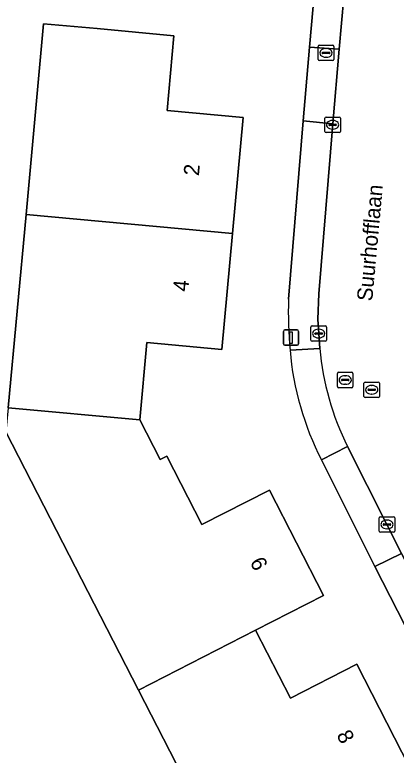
# Model space of a CAD drawing. Extents: x 162722 to 165104, y 384719 to 386284.
# Drawn here: x 163926.07 to 163950.78, y 385101.85 to 385149.88 of the extents above; entities that cross this region are included whole.
import ezdxf

# ---------------------------------------------------------------- set-up
doc = ezdxf.new("R2010")
doc.units = 0
for name, color, linetype in [('IMGEO_Brandkraan', 7, 'Continuous'), ('IMGEO_Erf', 7, 'Continuous'), ('IMGEO_Kolk', 7, 'Continuous'), ('IMGEO_Lichtmast', 7, 'Continuous'), ('IMGEO_Openbare_ruimte_label', 7, 'Continuous'), ('IMGEO_Pand', 7, 'Continuous'), ('IMGEO_Pand_nummerreeks', 7, 'Continuous'), ('IMGEO_Parkeervlak_open', 7, 'Continuous'), ('IMGEO_Rijbaan_lokaal_gesloten', 7, 'Continuous'), ('IMGEO_Rioolput', 7, 'Continuous'), ('IMGEO_Voetpad_open', 7, 'Continuous')]:
    doc.layers.add(name, color=color, linetype=linetype)

msp = doc.modelspace()

# ---------------------------------------------------------------- linework, layer by layer
at = {"layer": 'IMGEO_Brandkraan'}
for p, q in [((163945.732, 385146.978), (163945.732, 385147.83)), ((163945.807, 385147.904), (163946.659, 385147.904)), ((163946.22, 385147.684), (163946.245, 385147.684)), ((163946.733, 385147.83), (163946.733, 385146.978)), ((163945.991, 385147.398), (163945.991, 385147.41)), ((163946.429, 385147.361), (163946.031, 385147.361)), ((163946.034, 385147.447), (163946.432, 385147.447)), ((163946.475, 385147.41), (163946.475, 385147.398)), ((163946.659, 385146.904), (163945.807, 385146.904)), ((163946.243, 385147.124), (163946.218, 385147.124))]:
    msp.add_line(p, q, dxfattribs=at)
for points in [[(163945.732, 385146.978), (163945.732, 385147.83)], [(163945.807, 385147.904), (163946.659, 385147.904)], [(163946.733, 385147.83), (163946.733, 385146.978)], [(163946.659, 385146.904), (163945.807, 385146.904)]]:
    msp.add_lwpolyline(points, dxfattribs=at)
for centre, radius, start, end in [((163945.809, 385147.828), 0.0765, 91.552, 178.448), ((163945.809, 385147.828), 0.0765, 91.552, 178.448), ((163946.657, 385147.828), 0.0765, 1.552, 88.448), ((163946.657, 385147.828), 0.0765, 1.552, 88.448), ((163946.031, 385147.407), 0.0403, 85.8775, 175.7526), ((163946.028, 385147.397), 0.0366, 178.938, 274.7102), ((163946.432, 385147.404), 0.043, 264.8664, 352.4533), ((163946.436, 385147.409), 0.0386, 1.7309, 96.639), ((163945.809, 385146.98), 0.0765, 181.552, 268.448), ((163945.809, 385146.98), 0.0765, 181.552, 268.448), ((163946.657, 385146.98), 0.0765, 271.552, 358.448), ((163946.657, 385146.98), 0.0765, 271.552, 358.448)]:
    msp.add_arc(centre, radius, start, end, dxfattribs=at)
for centre, major_axis, ratio, start_param, end_param in [((163946.219, 385147.404), (-0.387, 0.002), 0.722429, 4.712389, 7.853982), ((163946.244, 385147.404), (-0.39, 0.002), 0.717154, 1.570796, 4.712389)]:
    msp.add_ellipse(centre, major_axis=major_axis, ratio=ratio, start_param=start_param, end_param=end_param, dxfattribs=at)
at = {"layer": 'IMGEO_Erf'}
for points in [[(163943.805, 385131.438), (163944.749, 385142.995), (163945.158, 385147.789), (163947.718, 385176.353)], [(163925.634, 385124.386), (163926.79, 385136.924), (163927.93, 385149.301), (163931.403, 385148.981), (163936.381, 385148.522), (163935.933, 385143.661), (163940.873, 385143.206), (163940.181, 385135.69), (163939.488, 385128.173), (163934.624, 385128.621), (163934.161, 385123.598), (163935.481, 385121.023), (163935.921, 385121.248), (163938.196, 385116.808), (163942.568, 385119.048), (163946.07, 385112.214), (163941.667, 385109.956), (163943.925, 385105.548), (163948.225, 385107.751), (163951.644, 385101.078)], [(163915.816, 385055.107), (163938.946, 385066.833), (163935.508, 385074.482), (163935.277, 385074.929), (163933.702, 385077.979), (163937.574, 385079.937), (163938.823, 385080.568), (163941.712, 385082.029), (163942.681, 385082.519), (163945.427, 385083.907), (163939.752, 385094.983), (163934.076, 385106.062), (163925.49, 385122.819)], [(163956.503, 385100.031), (163951.859, 385109.26), (163949.405, 385114.092), (163945.936, 385121.003)]]:
    msp.add_lwpolyline(points, dxfattribs=at)
for centre, radius, start, end in [((163970.652, 385130.542), 26.862, 178.0883, 185.1858), ((163963.285, 385129.817), 19.46, 185.0217, 206.9329)]:
    msp.add_arc(centre, radius, start, end, dxfattribs=at)
at = {"layer": 'IMGEO_Kolk'}
for p, q in [((163946.163, 385142.317), (163946.163, 385143.169)), ((163946.238, 385143.243), (163947.09, 385143.243)), ((163946.651, 385143.023), (163946.676, 385143.023)), ((163947.164, 385143.169), (163947.164, 385142.317)), ((163946.422, 385142.737), (163946.422, 385142.749)), ((163946.86, 385142.7), (163946.462, 385142.7)), ((163946.465, 385142.786), (163946.863, 385142.786)), ((163946.674, 385142.463), (163946.649, 385142.463)), ((163946.906, 385142.749), (163946.906, 385142.737)), ((163947.09, 385142.243), (163946.238, 385142.243)), ((163945.257, 385128.772), (163945.257, 385129.624)), ((163945.332, 385129.698), (163946.184, 385129.698)), ((163945.745, 385129.478), (163945.77, 385129.478)), ((163946.258, 385129.624), (163946.258, 385128.772)), ((163945.516, 385129.192), (163945.516, 385129.204)), ((163945.954, 385129.155), (163945.556, 385129.155)), ((163945.559, 385129.241), (163945.957, 385129.241)), ((163946, 385129.204), (163946, 385129.192)), ((163946.184, 385128.698), (163945.332, 385128.698)), ((163945.768, 385128.918), (163945.743, 385128.918)), ((163949.685, 385116.387), (163949.685, 385117.239)), ((163949.76, 385117.313), (163950.612, 385117.313)), ((163950.173, 385117.093), (163950.198, 385117.093)), ((163950.686, 385117.239), (163950.686, 385116.387)), ((163949.944, 385116.807), (163949.944, 385116.819)), ((163950.382, 385116.77), (163949.984, 385116.77)), ((163949.987, 385116.856), (163950.385, 385116.856)), ((163950.196, 385116.533), (163950.171, 385116.533)), ((163950.428, 385116.819), (163950.428, 385116.807)), ((163950.612, 385116.313), (163949.76, 385116.313))]:
    msp.add_line(p, q, dxfattribs=at)
for points in [[(163946.163, 385142.317), (163946.163, 385143.169)], [(163946.238, 385143.243), (163947.09, 385143.243)], [(163947.164, 385143.169), (163947.164, 385142.317)], [(163947.09, 385142.243), (163946.238, 385142.243)], [(163945.257, 385128.772), (163945.257, 385129.624)], [(163945.332, 385129.698), (163946.184, 385129.698)], [(163946.258, 385129.624), (163946.258, 385128.772)], [(163946.184, 385128.698), (163945.332, 385128.698)], [(163949.685, 385116.387), (163949.685, 385117.239)], [(163949.76, 385117.313), (163950.612, 385117.313)], [(163950.686, 385117.239), (163950.686, 385116.387)], [(163950.612, 385116.313), (163949.76, 385116.313)]]:
    msp.add_lwpolyline(points, dxfattribs=at)
for centre, radius, start, end in [((163946.24, 385143.167), 0.0765, 91.552, 178.448), ((163946.24, 385143.167), 0.0765, 91.552, 178.448), ((163947.088, 385143.167), 0.0765, 1.552, 88.448), ((163947.088, 385143.167), 0.0765, 1.552, 88.448), ((163946.462, 385142.746), 0.0403, 85.8775, 175.7526), ((163946.459, 385142.736), 0.0366, 178.938, 274.7102), ((163946.863, 385142.743), 0.043, 264.8664, 352.4533), ((163946.867, 385142.748), 0.0386, 1.7309, 96.639), ((163946.24, 385142.319), 0.0765, 181.552, 268.448), ((163946.24, 385142.319), 0.0765, 181.552, 268.448), ((163947.088, 385142.319), 0.0765, 271.552, 358.448), ((163947.088, 385142.319), 0.0765, 271.552, 358.448), ((163945.334, 385129.622), 0.0765, 91.552, 178.448), ((163945.334, 385129.622), 0.0765, 91.552, 178.448), ((163946.182, 385129.622), 0.0765, 1.552, 88.448), ((163946.182, 385129.622), 0.0765, 1.552, 88.448), ((163945.556, 385129.201), 0.0403, 85.8775, 175.7526), ((163945.553, 385129.191), 0.0366, 178.938, 274.7102), ((163945.957, 385129.198), 0.043, 264.8664, 352.4533), ((163945.961, 385129.203), 0.0386, 1.7309, 96.639), ((163945.334, 385128.774), 0.0765, 181.552, 268.448), ((163945.334, 385128.774), 0.0765, 181.552, 268.448), ((163946.182, 385128.774), 0.0765, 271.552, 358.448), ((163946.182, 385128.774), 0.0765, 271.552, 358.448), ((163949.762, 385117.237), 0.0765, 91.552, 178.448), ((163949.762, 385117.237), 0.0765, 91.552, 178.448), ((163950.61, 385117.237), 0.0765, 1.552, 88.448), ((163950.61, 385117.237), 0.0765, 1.552, 88.448), ((163949.984, 385116.816), 0.0403, 85.8775, 175.7526), ((163949.981, 385116.806), 0.0366, 178.938, 274.7102), ((163950.385, 385116.813), 0.043, 264.8664, 352.4533), ((163950.389, 385116.818), 0.0386, 1.7309, 96.639), ((163949.762, 385116.389), 0.0765, 181.552, 268.448), ((163949.762, 385116.389), 0.0765, 181.552, 268.448), ((163950.61, 385116.389), 0.0765, 271.552, 358.448), ((163950.61, 385116.389), 0.0765, 271.552, 358.448)]:
    msp.add_arc(centre, radius, start, end, dxfattribs=at)
for centre, major_axis, ratio, start_param, end_param in [((163946.65, 385142.743), (-0.387, 0.002), 0.722429, 4.712389, 7.853982), ((163946.675, 385142.743), (-0.39, 0.002), 0.717154, 1.570796, 4.712389), ((163945.744, 385129.198), (-0.387, 0.002), 0.722429, 4.712389, 7.853982), ((163945.769, 385129.198), (-0.39, 0.002), 0.717154, 1.570796, 4.712389), ((163950.172, 385116.813), (-0.387, 0.002), 0.722429, 4.712389, 7.853982), ((163950.197, 385116.813), (-0.39, 0.002), 0.717154, 1.570796, 4.712389)]:
    msp.add_ellipse(centre, major_axis=major_axis, ratio=ratio, start_param=start_param, end_param=end_param, dxfattribs=at)
at = {"layer": 'IMGEO_Lichtmast'}
for p, q in [((163943.569, 385129.439), (163944.359, 385129.439)), ((163944.359, 385129.439), (163943.569, 385129.439)), ((163943.469, 385128.539), (163943.469, 385129.339)), ((163943.469, 385129.339), (163943.469, 385128.539)), ((163944.459, 385129.339), (163944.459, 385128.539)), ((163944.459, 385128.539), (163944.459, 385129.339)), ((163944.359, 385128.439), (163943.569, 385128.439)), ((163943.569, 385128.439), (163944.359, 385128.439))]:
    msp.add_line(p, q, dxfattribs=at)
msp.add_lwpolyline([(163943.889, 385129.314), (163944.039, 385129.314), (163944.039, 385128.564), (163943.889, 385128.564), (163943.889, 385129.314)], dxfattribs=at)
for centre, start, end in [((163943.569, 385129.339), 90, 180), ((163943.569, 385129.339), 90, 180), ((163944.359, 385129.339), 0, 90), ((163944.359, 385129.339), 360, 90), ((163943.569, 385128.539), 180, 270), ((163943.569, 385128.539), 180, 270), ((163944.359, 385128.539), 270, 0), ((163944.359, 385128.539), 270, 0)]:
    msp.add_arc(centre, 0.1, start, end, dxfattribs=at)
at = {"layer": 'IMGEO_Pand'}
for points in [[(163940.181, 385135.69), (163940.873, 385143.206), (163935.933, 385143.661), (163936.381, 385148.522), (163931.403, 385148.981), (163927.93, 385149.301), (163926.79, 385136.924)], [(163934.161, 385123.598), (163934.624, 385128.621), (163939.488, 385128.173), (163940.181, 385135.69), (163926.79, 385136.924), (163925.634, 385124.386)], [(163946.07, 385112.214), (163942.568, 385119.048), (163938.196, 385116.808), (163935.921, 385121.248), (163935.481, 385121.023), (163934.161, 385123.598), (163925.634, 385124.386), (163925.49, 385122.819), (163934.076, 385106.062), (163941.667, 385109.956)], [(163948.225, 385107.751), (163943.925, 385105.548), (163941.667, 385109.956), (163934.076, 385106.062), (163939.752, 385094.983), (163951.644, 385101.078)]]:
    msp.add_lwpolyline(points, close=True, dxfattribs=at)
at = {"layer": 'IMGEO_Parkeervlak_open'}
msp.add_lwpolyline([(163947.718, 385176.353), (163945.158, 385147.789), (163947.078, 385147.645), (163948.291, 385161.171)], dxfattribs=at)
at = {"layer": 'IMGEO_Rijbaan_lokaal_gesloten'}
for points in [[(163949.567, 385176.071), (163949.298, 385173.033), (163948.291, 385161.171), (163947.078, 385147.645), (163946.667, 385142.814), (163945.777, 385131.775), (163945.709, 385130.132), (163945.758, 385129.198), (163945.828, 385128.235)], [(163947.623, 385121.871), (163950.186, 385116.813), (163951.121, 385114.939), (163953.559, 385110.107), (163955.301, 385106.72)]]:
    msp.add_lwpolyline(points, dxfattribs=at)
msp.add_arc((163963.895, 385129.896), 18.143, 185.2519, 206.2508, dxfattribs=at)
at = {"layer": 'IMGEO_Rioolput'}
for p, q in [((163946.976, 385125.761), (163946.976, 385126.613)), ((163947.051, 385126.687), (163947.903, 385126.687)), ((163947.977, 385126.613), (163947.977, 385125.761)), ((163947.235, 385126.181), (163947.235, 385126.193)), ((163947.673, 385126.144), (163947.275, 385126.144)), ((163947.278, 385126.23), (163947.676, 385126.23)), ((163947.464, 385126.467), (163947.489, 385126.467)), ((163947.719, 385126.193), (163947.719, 385126.181)), ((163947.903, 385125.687), (163947.051, 385125.687)), ((163947.487, 385125.907), (163947.462, 385125.907)), ((163948.695, 385125.126), (163948.695, 385125.978)), ((163948.77, 385126.052), (163949.622, 385126.052)), ((163948.997, 385125.595), (163949.395, 385125.595)), ((163949.183, 385125.832), (163949.208, 385125.832)), ((163949.696, 385125.978), (163949.696, 385125.126)), ((163948.954, 385125.546), (163948.954, 385125.558)), ((163949.392, 385125.509), (163948.994, 385125.509)), ((163949.206, 385125.272), (163949.181, 385125.272)), ((163949.438, 385125.558), (163949.438, 385125.546)), ((163949.622, 385125.052), (163948.77, 385125.052))]:
    msp.add_line(p, q, dxfattribs=at)
for points in [[(163946.976, 385125.761), (163946.976, 385126.613)], [(163947.051, 385126.687), (163947.903, 385126.687)], [(163947.977, 385126.613), (163947.977, 385125.761)], [(163947.903, 385125.687), (163947.051, 385125.687)], [(163948.695, 385125.126), (163948.695, 385125.978)], [(163948.77, 385126.052), (163949.622, 385126.052)], [(163949.696, 385125.978), (163949.696, 385125.126)], [(163949.622, 385125.052), (163948.77, 385125.052)]]:
    msp.add_lwpolyline(points, dxfattribs=at)
for centre, radius, start, end in [((163947.053, 385126.611), 0.0765, 91.552, 178.448), ((163947.053, 385126.611), 0.0765, 91.552, 178.448), ((163947.901, 385126.611), 0.0765, 1.552, 88.448), ((163947.901, 385126.611), 0.0765, 1.552, 88.448), ((163947.275, 385126.19), 0.0403, 85.8775, 175.7526), ((163947.272, 385126.18), 0.0366, 178.938, 274.7102), ((163947.676, 385126.187), 0.043, 264.8664, 352.4533), ((163947.68, 385126.192), 0.0386, 1.7309, 96.639), ((163947.053, 385125.763), 0.0765, 181.552, 268.448), ((163947.053, 385125.763), 0.0765, 181.552, 268.448), ((163947.901, 385125.763), 0.0765, 271.552, 358.448), ((163947.901, 385125.763), 0.0765, 271.552, 358.448), ((163948.772, 385125.976), 0.0765, 91.552, 178.448), ((163948.772, 385125.976), 0.0765, 91.552, 178.448), ((163948.994, 385125.555), 0.0403, 85.8775, 175.7526), ((163949.399, 385125.557), 0.0386, 1.7309, 96.639), ((163949.62, 385125.976), 0.0765, 1.552, 88.448), ((163949.62, 385125.976), 0.0765, 1.552, 88.448), ((163948.772, 385125.128), 0.0765, 181.552, 268.448), ((163948.772, 385125.128), 0.0765, 181.552, 268.448), ((163948.991, 385125.545), 0.0366, 178.938, 274.7102), ((163949.395, 385125.552), 0.043, 264.8664, 352.4533), ((163949.62, 385125.128), 0.0765, 271.552, 358.448), ((163949.62, 385125.128), 0.0765, 271.552, 358.448)]:
    msp.add_arc(centre, radius, start, end, dxfattribs=at)
for centre, major_axis, ratio, start_param, end_param in [((163947.463, 385126.187), (-0.387, 0.002), 0.722429, 4.712389, 7.853982), ((163947.488, 385126.187), (-0.39, 0.002), 0.717154, 1.570796, 4.712389), ((163949.182, 385125.552), (-0.387, 0.002), 0.722429, 4.712389, 7.853982), ((163949.207, 385125.552), (-0.39, 0.002), 0.717154, 1.570796, 4.712389)]:
    msp.add_ellipse(centre, major_axis=major_axis, ratio=ratio, start_param=start_param, end_param=end_param, dxfattribs=at)
at = {"layer": 'IMGEO_Voetpad_open'}
for points in [[(163945.158, 385147.789), (163944.749, 385142.995), (163946.667, 385142.814), (163947.078, 385147.645)], [(163945.936, 385121.003), (163949.405, 385114.092), (163951.121, 385114.939), (163950.186, 385116.813), (163947.623, 385121.871)], [(163949.405, 385114.092), (163951.859, 385109.26), (163953.559, 385110.107), (163951.121, 385114.939)]]:
    msp.add_lwpolyline(points, close=True, dxfattribs=at)
for points in [[(163943.9, 385128.114), (163945.828, 385128.235), (163945.758, 385129.198), (163945.709, 385130.132), (163945.777, 385131.775), (163946.667, 385142.814), (163944.749, 385142.995), (163943.805, 385131.438)], [(163945.828, 385128.235), (163943.9, 385128.114)], [(163945.936, 385121.003), (163947.623, 385121.871)]]:
    msp.add_lwpolyline(points, dxfattribs=at)
for centre, radius, start, end in [((163970.652, 385130.542), 26.862, 178.0883, 185.1858), ((163963.285, 385129.817), 19.46, 185.0217, 206.9329), ((163963.895, 385129.896), 18.143, 185.2519, 206.2508)]:
    msp.add_arc(centre, radius, start, end, dxfattribs=at)

# ---------------------------------------------------------------- texts
at = {"layer": 'IMGEO_Openbare_ruimte_label'}
msp.add_text('Suurhofflaan', height=1, rotation=84.7226, dxfattribs=at).set_placement((163949.227, 385131.266))
at = {"layer": 'IMGEO_Pand_nummerreeks'}
for s, rotation, p in [('2', 84.7362, (163937.992, 385139.403)), ('4', 84.7362, (163937.299, 385131.888)), ('6', 297.1323, (163941.274, 385114.379)), ('8', 297.1307, (163946.892, 385103.16))]:
    msp.add_text(s, height=1, rotation=rotation, dxfattribs=at).set_placement(p)

doc.saveas('drawing.dxf')
